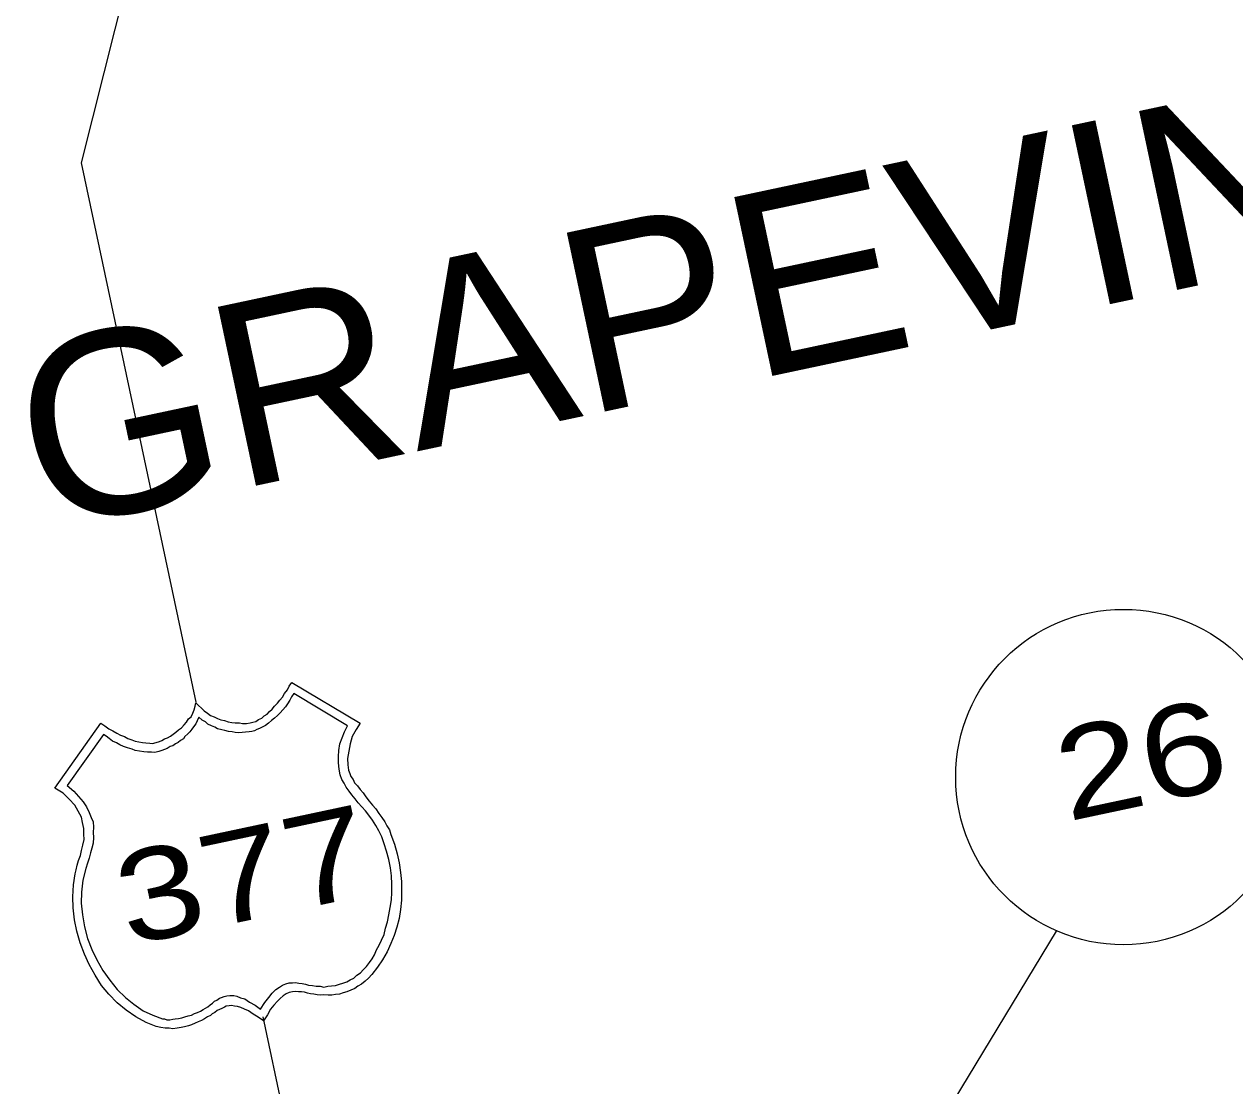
# Model space of a CAD drawing. Extents: x 2357218 to 2371708, y 6973728 to 6980157.
# Drawn here: x 2371426.3 to 2371493.9, y 6977700.8 to 6977760.1 of the extents above; entities that cross this region are included whole.
import ezdxf

# ---------------------------------------------------------------- set-up
doc = ezdxf.new("R2010")
doc.units = 0
doc.header["$LTSCALE"] = 2
doc.layers.add('62', color=7, linetype='Continuous', lineweight=13)
doc.layers.add('63', color=7, linetype='Continuous', lineweight=13)

msp = doc.modelspace()

# ---------------------------------------------------------------- linework, layer by layer
at = {"layer": '62'}
for p, q in [((2371435.922, 6977722.194), (2371429.517, 6977752.323)), ((2371477.331, 6977698.49), (2371483.957, 6977709.421)), ((2371448.774, 6977661.729), (2371439.656, 6977704.627))]:
    msp.add_line(p, q, dxfattribs=at)
for points in [[(2371429.517, 6977752.323), (2371444.613, 6977812.263), (2371444.656, 6977875.167)], [(2371428.034, 6977717.409), (2371430.599, 6977721.039), (2371430.818, 6977720.878), (2371431.034, 6977720.716), (2371431.266, 6977720.605), (2371431.48, 6977720.466), (2371431.684, 6977720.369), (2371431.912, 6977720.281), (2371432.094, 6977720.183), (2371432.32, 6977720.092), (2371432.52, 6977720.018), (2371432.709, 6977719.991), (2371432.926, 6977719.944), (2371433.111, 6977719.937), (2371433.323, 6977719.913), (2371433.487, 6977719.902), (2371433.686, 6977719.944), (2371433.879, 6977720.008), (2371434.008, 6977720.06), (2371434.146, 6977720.157), (2371434.317, 6977720.218), (2371434.484, 6977720.3), (2371434.641, 6977720.425), (2371434.782, 6977720.524), (2371434.939, 6977720.649), (2371435.097, 6977720.775), (2371435.245, 6977720.944), (2371435.374, 6977721.086), (2371435.496, 6977721.274), (2371435.634, 6977721.393), (2371435.726, 6977721.596), (2371435.804, 6977721.778), (2371435.854, 6977721.972), (2371435.905, 6977722.166), (2371436.054, 6977722.015), (2371436.22, 6977721.866), (2371436.37, 6977721.711), (2371436.555, 6977721.591), (2371436.719, 6977721.464), (2371436.922, 6977721.393), (2371437.103, 6977721.293), (2371437.302, 6977721.219), (2371437.497, 6977721.171), (2371437.696, 6977721.097), (2371437.908, 6977721.073), (2371438.098, 6977721.044), (2371438.329, 6977721.048), (2371438.497, 6977721.014), (2371438.726, 6977721.016), (2371438.925, 6977721.058), (2371439.078, 6977721.09), (2371439.254, 6977721.128), (2371439.393, 6977721.227), (2371439.583, 6977721.314), (2371439.716, 6977721.437), (2371439.88, 6977721.539), (2371440.012, 6977721.681), (2371440.167, 6977721.806), (2371440.295, 6977721.972), (2371440.465, 6977722.146), (2371440.591, 6977722.311), (2371440.739, 6977722.48), (2371440.855, 6977722.689), (2371441.021, 6977722.887), (2371441.113, 6977723.089), (2371441.254, 6977723.303), (2371445.073, 6977721.031), (2371444.847, 6977720.682), (2371444.631, 6977720.292), (2371444.513, 6977719.876), (2371444.439, 6977719.467), (2371444.363, 6977719.063), (2371444.395, 6977718.702), (2371444.432, 6977718.41), (2371444.498, 6977718.216), (2371444.559, 6977718.045), (2371444.683, 6977717.887), (2371444.767, 6977717.699), (2371444.921, 6977717.525), (2371445.078, 6977717.327), (2371445.234, 6977717.132), (2371445.395, 6977716.91), (2371445.584, 6977716.675), (2371445.767, 6977716.461), (2371445.949, 6977716.248), (2371446.121, 6977715.985), (2371446.282, 6977715.767), (2371446.45, 6977715.527), (2371446.568, 6977715.299), (2371446.705, 6977715.075), (2371446.783, 6977714.815), (2371446.988, 6977714.282), (2371447.15, 6977713.743), (2371447.257, 6977713.237), (2371447.327, 6977712.7), (2371447.39, 6977712.182), (2371447.388, 6977711.654), (2371447.381, 6977711.147), (2371447.33, 6977710.628), (2371447.251, 6977710.13), (2371447.124, 6977709.641)], [(2371446.143, 6977708.628), (2371446.268, 6977708.909), (2371446.407, 6977709.236), (2371446.493, 6977709.579), (2371446.599, 6977709.946), (2371446.681, 6977710.331), (2371446.755, 6977710.736), (2371446.825, 6977711.165), (2371446.85, 6977711.585), (2371446.846, 6977712.046), (2371446.817, 6977712.5), (2371446.767, 6977712.949), (2371446.669, 6977713.411), (2371446.546, 6977713.891), (2371446.411, 6977714.297), (2371446.283, 6977714.684), (2371446.12, 6977715.02), (2371445.941, 6977715.325), (2371445.763, 6977715.611), (2371445.567, 6977715.891), (2371445.378, 6977716.127), (2371445.169, 6977716.358), (2371444.96, 6977716.589), (2371444.798, 6977716.807), (2371444.613, 6977717.02), (2371444.452, 6977717.24), (2371444.291, 6977717.46), (2371444.173, 6977717.687), (2371444.06, 6977717.892), (2371443.961, 6977718.147), (2371443.895, 6977718.456), (2371443.865, 6977718.818), (2371443.859, 6977719.162), (2371443.879, 6977719.512), (2371443.938, 6977719.868), (2371444.073, 6977720.218), (2371444.209, 6977720.546), (2371444.367, 6977720.88), (2371441.365, 6977722.681), (2371441.239, 6977722.494), (2371441.143, 6977722.312), (2371441.026, 6977722.104), (2371440.899, 6977721.94), (2371440.751, 6977721.769), (2371440.604, 6977721.599), (2371440.451, 6977721.453), (2371440.296, 6977721.303), (2371440.118, 6977721.172), (2371439.965, 6977721.025), (2371439.786, 6977720.894), (2371439.641, 6977720.819), (2371439.453, 6977720.731), (2371439.303, 6977720.676), (2371439.181, 6977720.606), (2371439.024, 6977720.573), (2371438.872, 6977720.541), (2371438.67, 6977720.519), (2371438.489, 6977720.505), (2371438.308, 6977720.489), (2371438.096, 6977720.514), (2371437.93, 6977720.548), (2371437.716, 6977720.57), (2371437.522, 6977720.621), (2371437.353, 6977720.654), (2371437.108, 6977720.718), (2371436.956, 6977720.801), (2371436.776, 6977720.879), (2371436.574, 6977720.973), (2371436.431, 6977721.104), (2371436.247, 6977721.202), (2371436.072, 6977721.372), (2371435.976, 6977721.169), (2371435.901, 6977720.992), (2371435.775, 6977720.827), (2371435.667, 6977720.688), (2371435.559, 6977720.551), (2371435.445, 6977720.435), (2371435.293, 6977720.286), (2371435.204, 6977720.153), (2371435.038, 6977720.069), (2371434.904, 6977719.95), (2371434.761, 6977719.874), (2371434.621, 6977719.773), (2371434.468, 6977719.72), (2371434.307, 6977719.614), (2371434.157, 6977719.56), (2371434.008, 6977719.507), (2371433.837, 6977719.447), (2371433.616, 6977719.399), (2371433.431, 6977719.407), (2371433.202, 6977719.404), (2371432.991, 6977719.428), (2371432.751, 6977719.469), (2371432.513, 6977719.509), (2371432.335, 6977719.587), (2371432.09, 6977719.652), (2371431.869, 6977719.72), (2371431.664, 6977719.813), (2371431.478, 6977719.935), (2371431.251, 6977720.025), (2371431.061, 6977720.168)], [(2371430.735, 6977720.4), (2371428.719, 6977717.554), (2371429.082, 6977717.239), (2371429.355, 6977716.929), (2371429.603, 6977716.637), (2371429.799, 6977716.358), (2371429.938, 6977716.041), (2371430.061, 6977715.769), (2371430.162, 6977715.515), (2371430.18, 6977715.22), (2371430.174, 6977714.919), (2371430.186, 6977714.646), (2371430.159, 6977714.339), (2371430.084, 6977714.047), (2371430.026, 6977713.783), (2371429.948, 6977713.491), (2371429.845, 6977713.217), (2371429.749, 6977712.92), (2371429.588, 6977712.264), (2371429.521, 6977711.604), (2371429.493, 6977710.979), (2371429.564, 6977710.325), (2371429.681, 6977709.662), (2371429.845, 6977709.005), (2371430.09, 6977708.39), (2371430.375, 6977707.81), (2371430.709, 6977707.212), (2371431.101, 6977706.675), (2371431.507, 6977706.161), (2371431.971, 6977705.708), (2371432.438, 6977705.348), (2371432.955, 6977704.975), (2371433.491, 6977704.721), (2371434.042, 6977704.516), (2371434.158, 6977704.517), (2371434.282, 6977704.475), (2371434.444, 6977704.464), (2371434.62, 6977704.501), (2371434.753, 6977704.529), (2371434.933, 6977704.545), (2371435.109, 6977704.583), (2371435.281, 6977704.641), (2371435.48, 6977704.684), (2371435.657, 6977704.721), (2371435.818, 6977704.825), (2371435.99, 6977704.884), (2371436.161, 6977704.943), (2371436.3, 6977705.042), (2371436.443, 6977705.119), (2371436.569, 6977705.189), (2371436.705, 6977705.312), (2371436.822, 6977705.405), (2371436.939, 6977705.5), (2371437.063, 6977705.57), (2371437.226, 6977705.677), (2371437.329, 6977705.721), (2371437.479, 6977705.774), (2371437.634, 6977705.808), (2371437.791, 6977705.817), (2371438.021, 6977705.822), (2371438.19, 6977705.789), (2371438.394, 6977705.694), (2371438.639, 6977705.631), (2371438.904, 6977705.458), (2371439.215, 6977705.294), (2371439.519, 6977705.058), (2371439.761, 6977705.431), (2371439.978, 6977705.709), (2371440.155, 6977705.953), (2371440.367, 6977706.158), (2371440.567, 6977706.293), (2371440.729, 6977706.398), (2371440.919, 6977706.484), (2371441.115, 6977706.524), (2371441.295, 6977706.541), (2371441.455, 6977706.552), (2371441.645, 6977706.522), (2371441.833, 6977706.494), (2371442.025, 6977706.467), (2371442.198, 6977706.41), (2371442.41, 6977706.386), (2371442.626, 6977706.34), (2371442.833, 6977706.339), (2371443.052, 6977706.291), (2371443.271, 6977706.338), (2371443.473, 6977706.358), (2371443.7, 6977706.385), (2371443.915, 6977706.452), (2371444.108, 6977706.516), (2371444.324, 6977706.586), (2371444.508, 6977706.693), (2371444.719, 6977706.786), (2371444.887, 6977706.959), (2371445.091, 6977707.095), (2371445.237, 6977707.264), (2371445.431, 6977707.441), (2371445.591, 6977707.659), (2371445.751, 6977707.879), (2371445.868, 6977708.088), (2371445.992, 6977708.369), (2371446.143, 6977708.628)], [(2371431.061, 6977720.168), (2371430.894, 6977720.296), (2371430.735, 6977720.4)], [(2371428.833, 6977716.795), (2371428.489, 6977717.114), (2371428.034, 6977717.409)], [(2371447.124, 6977709.641), (2371446.972, 6977709.172), (2371446.793, 6977708.72), (2371446.589, 6977708.264), (2371446.317, 6977707.813), (2371446.034, 6977707.41), (2371445.731, 6977707.001), (2371445.545, 6977706.799), (2371445.354, 6977706.621), (2371445.156, 6977706.464), (2371444.949, 6977706.35), (2371444.77, 6977706.221), (2371444.558, 6977706.129), (2371444.327, 6977706.035), (2371444.132, 6977705.969), (2371443.919, 6977705.903), (2371443.694, 6977705.878), (2371443.492, 6977705.835), (2371443.285, 6977705.837), (2371443.052, 6977705.856), (2371442.872, 6977705.84), (2371442.682, 6977705.868), (2371442.491, 6977705.898), (2371442.301, 6977705.927), (2371442.133, 6977705.959), (2371441.959, 6977706.015), (2371441.797, 6977706.027), (2371441.633, 6977706.038), (2371441.448, 6977706.044), (2371441.291, 6977706.033), (2371441.113, 6977705.996), (2371440.948, 6977705.916), (2371440.784, 6977705.811), (2371440.61, 6977705.66), (2371440.457, 6977705.511), (2371440.252, 6977705.283), (2371440.068, 6977705.061), (2371439.906, 6977704.749), (2371439.681, 6977704.403), (2371439.384, 6977704.616), (2371439.092, 6977704.785), (2371438.848, 6977704.962), (2371438.622, 6977705.053), (2371438.418, 6977705.147), (2371438.217, 6977705.219), (2371438.055, 6977705.231), (2371437.886, 6977705.265), (2371437.751, 6977705.256), (2371437.598, 6977705.224), (2371437.492, 6977705.179), (2371437.346, 6977705.103), (2371437.218, 6977705.051), (2371437.096, 6977704.981), (2371436.955, 6977704.883), (2371436.812, 6977704.805), (2371436.715, 6977704.715), (2371436.548, 6977704.633), (2371436.386, 6977704.531), (2371436.224, 6977704.428), (2371436.031, 6977704.363), (2371435.865, 6977704.281), (2371435.655, 6977704.191), (2371435.484, 6977704.13), (2371435.261, 6977704.083), (2371435.087, 6977704.046), (2371434.865, 6977704.001), (2371434.62, 6977703.97), (2371434.407, 6977703.994), (2371434.178, 6977703.993), (2371433.938, 6977704.033), (2371433.693, 6977704.098), (2371433.117, 6977704.319), (2371432.544, 6977704.636), (2371432.006, 6977705.004), (2371431.504, 6977705.424), (2371431.032, 6977705.901), (2371430.632, 6977706.391), (2371430.28, 6977706.958), (2371429.946, 6977707.556), (2371429.683, 6977708.142), (2371429.437, 6977708.758), (2371429.252, 6977709.41), (2371429.116, 6977710.048), (2371429.042, 6977710.722), (2371429.028, 6977711.34), (2371429.07, 6977711.995), (2371429.17, 6977712.613), (2371429.212, 6977712.85), (2371429.274, 6977713.095), (2371429.354, 6977713.364), (2371429.457, 6977713.638), (2371429.513, 6977713.926), (2371429.587, 6977714.219), (2371429.657, 6977714.533), (2371429.641, 6977714.83), (2371429.643, 6977715.15), (2371429.572, 6977715.482), (2371429.507, 6977715.789), (2371429.321, 6977716.117), (2371429.136, 6977716.447), (2371428.833, 6977716.795)]]:
    msp.add_lwpolyline(points, dxfattribs=at)
msp.add_circle((2371487.691, 6977718.022), 9.364, dxfattribs=at)
at = {"layer": '63'}
for p, q in [((2371435.922, 6977722.194), (2371429.517, 6977752.323)), ((2371477.331, 6977698.49), (2371483.957, 6977709.421)), ((2371448.774, 6977661.729), (2371439.656, 6977704.627))]:
    msp.add_line(p, q, dxfattribs=at)
for points in [[(2371429.517, 6977752.323), (2371444.613, 6977812.263), (2371444.656, 6977875.167)], [(2371428.034, 6977717.409), (2371430.599, 6977721.039), (2371430.818, 6977720.878), (2371431.034, 6977720.716), (2371431.266, 6977720.605), (2371431.48, 6977720.466), (2371431.684, 6977720.369), (2371431.912, 6977720.281), (2371432.094, 6977720.183), (2371432.32, 6977720.092), (2371432.52, 6977720.018), (2371432.709, 6977719.991), (2371432.926, 6977719.944), (2371433.111, 6977719.937), (2371433.323, 6977719.913), (2371433.487, 6977719.902), (2371433.686, 6977719.944), (2371433.879, 6977720.008), (2371434.008, 6977720.06), (2371434.146, 6977720.157), (2371434.317, 6977720.218), (2371434.484, 6977720.3), (2371434.641, 6977720.425), (2371434.782, 6977720.524), (2371434.939, 6977720.649), (2371435.097, 6977720.775), (2371435.245, 6977720.944), (2371435.374, 6977721.086), (2371435.496, 6977721.274), (2371435.634, 6977721.393), (2371435.726, 6977721.596), (2371435.804, 6977721.778), (2371435.854, 6977721.972), (2371435.905, 6977722.166), (2371436.054, 6977722.015), (2371436.22, 6977721.866), (2371436.37, 6977721.711), (2371436.555, 6977721.591), (2371436.719, 6977721.464), (2371436.922, 6977721.393), (2371437.103, 6977721.293), (2371437.302, 6977721.219), (2371437.497, 6977721.171), (2371437.696, 6977721.097), (2371437.908, 6977721.073), (2371438.098, 6977721.044), (2371438.329, 6977721.048), (2371438.497, 6977721.014), (2371438.726, 6977721.016), (2371438.925, 6977721.058), (2371439.078, 6977721.09), (2371439.254, 6977721.128), (2371439.393, 6977721.227), (2371439.583, 6977721.314), (2371439.716, 6977721.437), (2371439.88, 6977721.539), (2371440.012, 6977721.681), (2371440.167, 6977721.806), (2371440.295, 6977721.972), (2371440.465, 6977722.146), (2371440.591, 6977722.311), (2371440.739, 6977722.48), (2371440.855, 6977722.689), (2371441.021, 6977722.887), (2371441.113, 6977723.089), (2371441.254, 6977723.303), (2371445.073, 6977721.031), (2371444.847, 6977720.682), (2371444.631, 6977720.292), (2371444.513, 6977719.876), (2371444.439, 6977719.467), (2371444.363, 6977719.063), (2371444.395, 6977718.702), (2371444.432, 6977718.41), (2371444.498, 6977718.216), (2371444.559, 6977718.045), (2371444.683, 6977717.887), (2371444.767, 6977717.699), (2371444.921, 6977717.525), (2371445.078, 6977717.327), (2371445.234, 6977717.132), (2371445.395, 6977716.91), (2371445.584, 6977716.675), (2371445.767, 6977716.461), (2371445.949, 6977716.248), (2371446.121, 6977715.985), (2371446.282, 6977715.767), (2371446.45, 6977715.527), (2371446.568, 6977715.299), (2371446.705, 6977715.075), (2371446.783, 6977714.815), (2371446.988, 6977714.282), (2371447.15, 6977713.743), (2371447.257, 6977713.237), (2371447.327, 6977712.7), (2371447.39, 6977712.182), (2371447.388, 6977711.654), (2371447.381, 6977711.147), (2371447.33, 6977710.628), (2371447.251, 6977710.13), (2371447.124, 6977709.641)], [(2371446.143, 6977708.628), (2371446.268, 6977708.909), (2371446.407, 6977709.236), (2371446.493, 6977709.579), (2371446.599, 6977709.946), (2371446.681, 6977710.331), (2371446.755, 6977710.736), (2371446.825, 6977711.165), (2371446.85, 6977711.585), (2371446.846, 6977712.046), (2371446.817, 6977712.5), (2371446.767, 6977712.949), (2371446.669, 6977713.411), (2371446.546, 6977713.891), (2371446.411, 6977714.297), (2371446.283, 6977714.684), (2371446.12, 6977715.02), (2371445.941, 6977715.325), (2371445.763, 6977715.611), (2371445.567, 6977715.891), (2371445.378, 6977716.127), (2371445.169, 6977716.358), (2371444.96, 6977716.589), (2371444.798, 6977716.807), (2371444.613, 6977717.02), (2371444.452, 6977717.24), (2371444.291, 6977717.46), (2371444.173, 6977717.687), (2371444.06, 6977717.892), (2371443.961, 6977718.147), (2371443.895, 6977718.456), (2371443.865, 6977718.818), (2371443.859, 6977719.162), (2371443.879, 6977719.512), (2371443.938, 6977719.868), (2371444.073, 6977720.218), (2371444.209, 6977720.546), (2371444.367, 6977720.88), (2371441.365, 6977722.681), (2371441.239, 6977722.494), (2371441.143, 6977722.312), (2371441.026, 6977722.104), (2371440.899, 6977721.94), (2371440.751, 6977721.769), (2371440.604, 6977721.599), (2371440.451, 6977721.453), (2371440.296, 6977721.303), (2371440.118, 6977721.172), (2371439.965, 6977721.025), (2371439.786, 6977720.894), (2371439.641, 6977720.819), (2371439.453, 6977720.731), (2371439.303, 6977720.676), (2371439.181, 6977720.606), (2371439.024, 6977720.573), (2371438.872, 6977720.541), (2371438.67, 6977720.519), (2371438.489, 6977720.505), (2371438.308, 6977720.489), (2371438.096, 6977720.514), (2371437.93, 6977720.548), (2371437.716, 6977720.57), (2371437.522, 6977720.621), (2371437.353, 6977720.654), (2371437.108, 6977720.718), (2371436.956, 6977720.801), (2371436.776, 6977720.879), (2371436.574, 6977720.973), (2371436.431, 6977721.104), (2371436.247, 6977721.202), (2371436.072, 6977721.372), (2371435.976, 6977721.169), (2371435.901, 6977720.992), (2371435.775, 6977720.827), (2371435.667, 6977720.688), (2371435.559, 6977720.551), (2371435.445, 6977720.435), (2371435.293, 6977720.286), (2371435.204, 6977720.153), (2371435.038, 6977720.069), (2371434.904, 6977719.95), (2371434.761, 6977719.874), (2371434.621, 6977719.773), (2371434.468, 6977719.72), (2371434.307, 6977719.614), (2371434.157, 6977719.56), (2371434.008, 6977719.507), (2371433.837, 6977719.447), (2371433.616, 6977719.399), (2371433.431, 6977719.407), (2371433.202, 6977719.404), (2371432.991, 6977719.428), (2371432.751, 6977719.469), (2371432.513, 6977719.509), (2371432.335, 6977719.587), (2371432.09, 6977719.652), (2371431.869, 6977719.72), (2371431.664, 6977719.813), (2371431.478, 6977719.935), (2371431.251, 6977720.025), (2371431.061, 6977720.168)], [(2371430.735, 6977720.4), (2371428.719, 6977717.554), (2371429.082, 6977717.239), (2371429.355, 6977716.929), (2371429.603, 6977716.637), (2371429.799, 6977716.358), (2371429.938, 6977716.041), (2371430.061, 6977715.769), (2371430.162, 6977715.515), (2371430.18, 6977715.22), (2371430.174, 6977714.919), (2371430.186, 6977714.646), (2371430.159, 6977714.339), (2371430.084, 6977714.047), (2371430.026, 6977713.783), (2371429.948, 6977713.491), (2371429.845, 6977713.217), (2371429.749, 6977712.92), (2371429.588, 6977712.264), (2371429.521, 6977711.604), (2371429.493, 6977710.979), (2371429.564, 6977710.325), (2371429.681, 6977709.662), (2371429.845, 6977709.005), (2371430.09, 6977708.39), (2371430.375, 6977707.81), (2371430.709, 6977707.212), (2371431.101, 6977706.675), (2371431.507, 6977706.161), (2371431.971, 6977705.708), (2371432.438, 6977705.348), (2371432.955, 6977704.975), (2371433.491, 6977704.721), (2371434.042, 6977704.516), (2371434.158, 6977704.517), (2371434.282, 6977704.475), (2371434.444, 6977704.464), (2371434.62, 6977704.501), (2371434.753, 6977704.529), (2371434.933, 6977704.545), (2371435.109, 6977704.583), (2371435.281, 6977704.641), (2371435.48, 6977704.684), (2371435.657, 6977704.721), (2371435.818, 6977704.825), (2371435.99, 6977704.884), (2371436.161, 6977704.943), (2371436.3, 6977705.042), (2371436.443, 6977705.119), (2371436.569, 6977705.189), (2371436.705, 6977705.312), (2371436.822, 6977705.405), (2371436.939, 6977705.5), (2371437.063, 6977705.57), (2371437.226, 6977705.677), (2371437.329, 6977705.721), (2371437.479, 6977705.774), (2371437.634, 6977705.808), (2371437.791, 6977705.817), (2371438.021, 6977705.822), (2371438.19, 6977705.789), (2371438.394, 6977705.694), (2371438.639, 6977705.631), (2371438.904, 6977705.458), (2371439.215, 6977705.294), (2371439.519, 6977705.058), (2371439.761, 6977705.431), (2371439.978, 6977705.709), (2371440.155, 6977705.953), (2371440.367, 6977706.158), (2371440.567, 6977706.293), (2371440.729, 6977706.398), (2371440.919, 6977706.484), (2371441.115, 6977706.524), (2371441.295, 6977706.541), (2371441.455, 6977706.552), (2371441.645, 6977706.522), (2371441.833, 6977706.494), (2371442.025, 6977706.467), (2371442.198, 6977706.41), (2371442.41, 6977706.386), (2371442.626, 6977706.34), (2371442.833, 6977706.339), (2371443.052, 6977706.291), (2371443.271, 6977706.338), (2371443.473, 6977706.358), (2371443.7, 6977706.385), (2371443.915, 6977706.452), (2371444.108, 6977706.516), (2371444.324, 6977706.586), (2371444.508, 6977706.693), (2371444.719, 6977706.786), (2371444.887, 6977706.959), (2371445.091, 6977707.095), (2371445.237, 6977707.264), (2371445.431, 6977707.441), (2371445.591, 6977707.659), (2371445.751, 6977707.879), (2371445.868, 6977708.088), (2371445.992, 6977708.369), (2371446.143, 6977708.628)], [(2371431.061, 6977720.168), (2371430.894, 6977720.296), (2371430.735, 6977720.4)], [(2371428.833, 6977716.795), (2371428.489, 6977717.114), (2371428.034, 6977717.409)], [(2371447.124, 6977709.641), (2371446.972, 6977709.172), (2371446.793, 6977708.72), (2371446.589, 6977708.264), (2371446.317, 6977707.813), (2371446.034, 6977707.41), (2371445.731, 6977707.001), (2371445.545, 6977706.799), (2371445.354, 6977706.621), (2371445.156, 6977706.464), (2371444.949, 6977706.35), (2371444.77, 6977706.221), (2371444.558, 6977706.129), (2371444.327, 6977706.035), (2371444.132, 6977705.969), (2371443.919, 6977705.903), (2371443.694, 6977705.878), (2371443.492, 6977705.835), (2371443.285, 6977705.837), (2371443.052, 6977705.856), (2371442.872, 6977705.84), (2371442.682, 6977705.868), (2371442.491, 6977705.898), (2371442.301, 6977705.927), (2371442.133, 6977705.959), (2371441.959, 6977706.015), (2371441.797, 6977706.027), (2371441.633, 6977706.038), (2371441.448, 6977706.044), (2371441.291, 6977706.033), (2371441.113, 6977705.996), (2371440.948, 6977705.916), (2371440.784, 6977705.811), (2371440.61, 6977705.66), (2371440.457, 6977705.511), (2371440.252, 6977705.283), (2371440.068, 6977705.061), (2371439.906, 6977704.749), (2371439.681, 6977704.403), (2371439.384, 6977704.616), (2371439.092, 6977704.785), (2371438.848, 6977704.962), (2371438.622, 6977705.053), (2371438.418, 6977705.147), (2371438.217, 6977705.219), (2371438.055, 6977705.231), (2371437.886, 6977705.265), (2371437.751, 6977705.256), (2371437.598, 6977705.224), (2371437.492, 6977705.179), (2371437.346, 6977705.103), (2371437.218, 6977705.051), (2371437.096, 6977704.981), (2371436.955, 6977704.883), (2371436.812, 6977704.805), (2371436.715, 6977704.715), (2371436.548, 6977704.633), (2371436.386, 6977704.531), (2371436.224, 6977704.428), (2371436.031, 6977704.363), (2371435.865, 6977704.281), (2371435.655, 6977704.191), (2371435.484, 6977704.13), (2371435.261, 6977704.083), (2371435.087, 6977704.046), (2371434.865, 6977704.001), (2371434.62, 6977703.97), (2371434.407, 6977703.994), (2371434.178, 6977703.993), (2371433.938, 6977704.033), (2371433.693, 6977704.098), (2371433.117, 6977704.319), (2371432.544, 6977704.636), (2371432.006, 6977705.004), (2371431.504, 6977705.424), (2371431.032, 6977705.901), (2371430.632, 6977706.391), (2371430.28, 6977706.958), (2371429.946, 6977707.556), (2371429.683, 6977708.142), (2371429.437, 6977708.758), (2371429.252, 6977709.41), (2371429.116, 6977710.048), (2371429.042, 6977710.722), (2371429.028, 6977711.34), (2371429.07, 6977711.995), (2371429.17, 6977712.613), (2371429.212, 6977712.85), (2371429.274, 6977713.095), (2371429.354, 6977713.364), (2371429.457, 6977713.638), (2371429.513, 6977713.926), (2371429.587, 6977714.219), (2371429.657, 6977714.533), (2371429.641, 6977714.83), (2371429.643, 6977715.15), (2371429.572, 6977715.482), (2371429.507, 6977715.789), (2371429.321, 6977716.117), (2371429.136, 6977716.447), (2371428.833, 6977716.795)]]:
    msp.add_lwpolyline(points, dxfattribs=at)
msp.add_circle((2371487.691, 6977718.022), 9.364, dxfattribs=at)

# ---------------------------------------------------------------- texts
at = {"layer": '62'}
for s, height, width, p in [('GRAPEVINE', 10.21, 1.05, (2371427.199, 6977731.726)), ('26', 5.099, 1.25, (2371484.566, 6977715.532)), ('377', 5.108, 1.25, (2371432.095, 6977708.588))]:
    msp.add_text(s, height=height, rotation=12, dxfattribs=dict(at, width=width)).set_placement(p)
at = {"layer": '63'}
for s, height, width, p in [('GRAPEVINE', 10.21, 1.05, (2371427.199, 6977731.726)), ('26', 5.099, 1.25, (2371484.566, 6977715.532)), ('377', 5.108, 1.25, (2371432.095, 6977708.588))]:
    msp.add_text(s, height=height, rotation=12, dxfattribs=dict(at, width=width)).set_placement(p)

doc.saveas('drawing.dxf')
